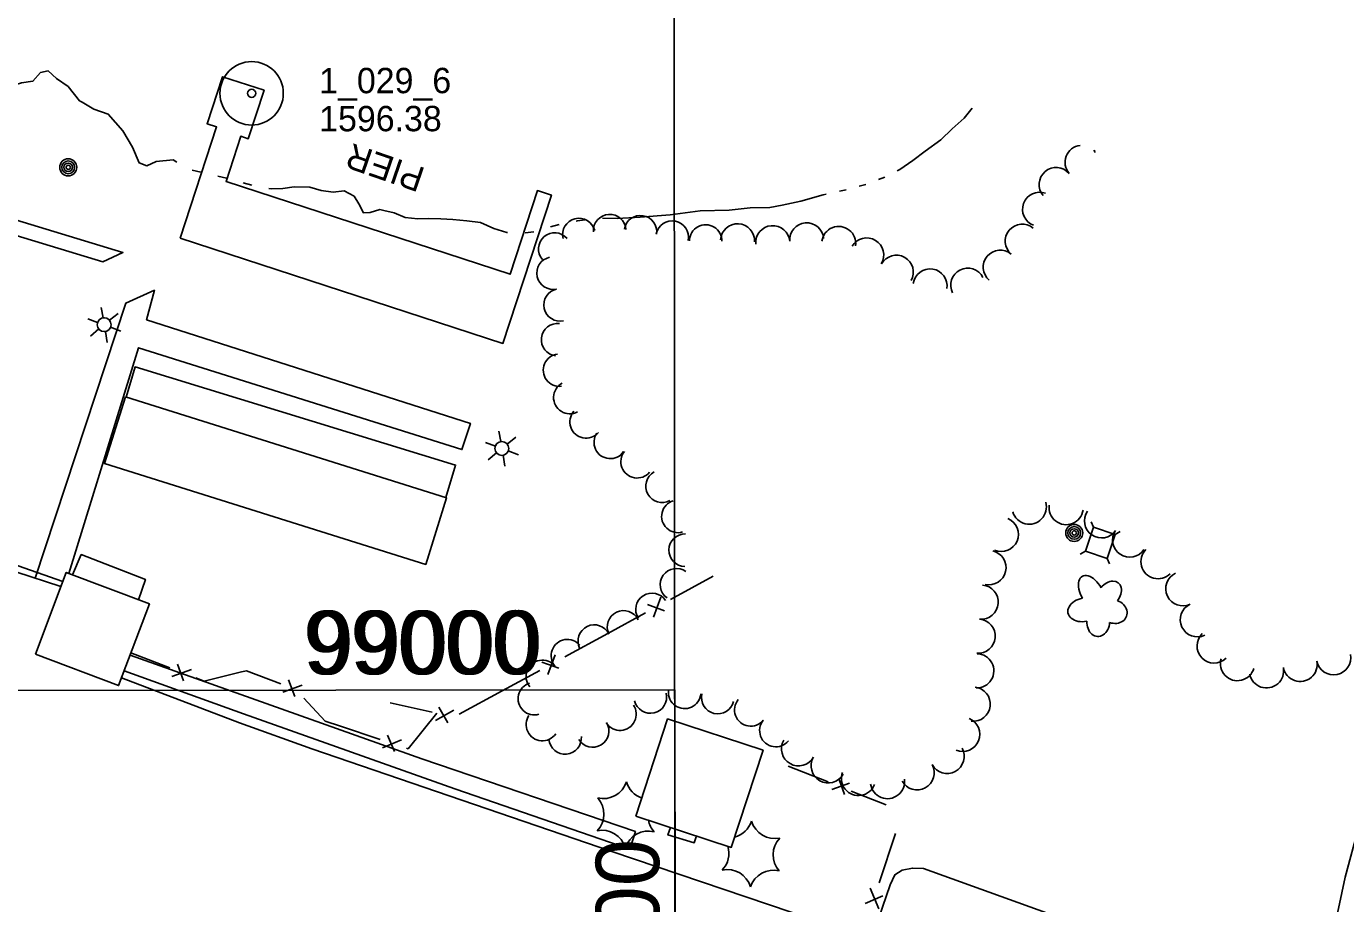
# Model space of a CAD drawing. Extents: x 189384 to 193282, y 256970 to 260388.
# Drawn here: x 191493.2 to 191805.5, y 258961.6 to 259169.2 of the extents above; entities that cross this region are included whole.
import ezdxf

# ---------------------------------------------------------------- set-up
doc = ezdxf.new("R2010")
doc.units = 0
for name, color, linetype in [('E_DWY', 7, 'Continuous'), ('E_LAND_Vegetation', 7, 'Continuous'), ('E_MAP_GridLines', 7, 'Continuous'), ('E_MAP_PassPoints', 7, 'Continuous'), ('E_MISCPROP', 7, 'Continuous'), ('E_MISCPROP_HvyDash', 7, 'Continuous'), ('E_MISCPROP_HvyLine', 7, 'Continuous'), ('E_MISCPROP_Railing', 7, 'Continuous'), ('E_PATH_Sidewalk', 7, 'Continuous'), ('E_UTL_AboveGroundPipe', 7, 'Continuous'), ('E_WTR', 7, 'Continuous'), ('E_WTR_Dock_Pier', 7, 'Continuous'), ('E_WTR_Text', 7, 'Continuous')]:
    doc.layers.add(name, color=color, linetype=linetype)

# ---------------------------------------------------------------- blocks, each defined once
blk = doc.blocks.new('PP')
at = {"layer": 'E_MAP_PassPoints'}
for radius in [7.5, 0.96]:
    blk.add_circle((0, 0), radius, dxfattribs=at)
blk = doc.blocks.new('PIER')
at = {"layer": 'E_WTR_Text'}
blk.add_text('PIER', height=6, rotation=0.0001, dxfattribs=at).set_placement((0.24, -2.75))
blk = doc.blocks.new('POLE')
at = {"layer": 'E_MISCPROP'}
for radius in [2.02, 1.51, 1.01, 0.504]:
    blk.add_circle((0.03, -0.09), radius, dxfattribs=at)
blk = doc.blocks.new('LTP')
at = {"layer": 'E_MISCPROP'}
for p, q in [((-0.78, 1.46), (-1.98, 3.76)), ((0.86, 1.37), (2.22, 3.6)), ((-1.61, 0.09), (-4.22, 0.17)), ((1.66, 0), (4.18, -0.06)), ((-0.86, -1.4), (-2.22, -3.59)), ((0.78, -1.44), (2.02, -3.62))]:
    blk.add_line(p, q, dxfattribs=at)
blk.add_circle((0.02, 0.01), 1.64, dxfattribs=at)
blk = doc.blocks.new('POLE_1')
at = {"layer": 'E_MISCPROP'}
for radius in [2.02, 1.51, 1.01, 0.504]:
    blk.add_circle((0.03, -0.09), radius, dxfattribs=at)
blk = doc.blocks.new('PED')
at = {"layer": 'E_UTL_AboveGroundPipe'}
for p, q in [((-2.34, 2.71), (-3.29, 3.77)), ((3.06, 2.71), (4.02, 3.77)), ((-3.29, -4.35), (-2.34, -3.29)), ((4.02, -4.35), (3.06, -3.29))]:
    blk.add_line(p, q, dxfattribs=at)
blk.add_lwpolyline([(-2.34, -3.29), (3.06, -3.29), (3.06, 2.71), (-2.34, 2.71)], close=True, dxfattribs=at)
blk = doc.blocks.new('TREE')
at = {"layer": 'E_LAND_Vegetation'}
for centre, major_axis, ratio in [((-1.07, 3.38), (0.91, -3.32), 0.782863), ((2.88, 1.66), (-3.52, -1.95), 0.691916), ((-3.74, -0.07), (3.29, -0.08), 0.832022), ((-1.48, -3.66), (1.2, 3.24), 0.716896), ((2.54, -2.64), (-3.34, 3.06), 0.560249)]:
    blk.add_ellipse(centre, major_axis=major_axis, ratio=ratio, start_param=1.570796, end_param=4.712389, dxfattribs=at)

msp = doc.modelspace()

# ---------------------------------------------------------------- linework, layer by layer
at = {"layer": 'E_DWY'}
for points in [[(191501.35, 259036.59), (191479.96, 259043.57)], [(191682.66, 258922.4), (191681.57, 258919.82), (191680.85, 258919.25), (191679.6, 258918.89), (191678.51, 258918.91), (191677.77, 258919.33), (191677.07, 258920.57), (191676.84, 258921.92), (191677.19, 258923.18), (191686.53, 258953.16), (191686.41, 258954.33), (191685.67, 258955.42), (191684.69, 258956.02), (191631.75, 258973.9), (191560.77, 258998.17), (191543.64, 259004.34), (191515.7, 259014.96)], [(191682.66, 258922.4), (191697.63, 258965.98), (191698.76, 258968.4), (191700.51, 258969.51), (191702.94, 258969.96), (191705.59, 258969.84), (191795.73, 258937.33), (191797.22, 258936.96), (191798.22, 258936.97), (191799.23, 258937.68), (191800.15, 258938.79), (191800.88, 258941.07), (191801.39, 258946.78), (191802.75, 258955.61), (191805.35, 258967.79), (191808.61, 258979.78)]]:
    msp.add_lwpolyline(points, dxfattribs=at)
at = {"layer": 'E_LAND_Vegetation'}
for centre, radius, start, end in [((191743.1, 259136.99), 4.03, 97.0163, 220.6033), ((191749.43, 259141.75), 4.03, 207.8807, 216.409), ((191743.1, 259136.99), 4.03, 40.6033, 44.7846), ((191736.97, 259131.74), 4.03, 40.6033, 220.6033), ((191733.02, 259125.89), 4.03, 69.7676, 249.7676), ((191623.98, 259119.9), 3.85, 13.9298, 193.9298), ((191631.27, 259120.84), 3.85, 3.7621, 183.7621), ((191638.56, 259120.57), 3.85, 351.0761, 171.0761), ((191618.25, 259116.49), 3.85, 40.642, 220.642), ((191646.06, 259119.29), 3.85, 348.3917, 168.3917), ((191654, 259118.38), 3.85, 358.8551, 178.8551), ((191661.55, 259118.43), 4.03, 356.859, 176.859), ((191669.86, 259117.99), 4.03, 4.6262, 184.6262), ((191677.9, 259118.64), 4.03, 4.6262, 184.6262), ((191685.49, 259117.8), 4.03, 352.0997, 172.0997), ((191728.92, 259118.33), 4.03, 49.7405, 229.7405), ((191692.11, 259115.07), 4.03, 329.0382, 149.0382), ((191617.86, 259110.76), 3.85, 102.5104, 282.5104), ((191699.13, 259110.99), 4.03, 330.7807, 150.7807), ((191723.71, 259112.17), 4.03, 49.7405, 229.7405), ((191707.12, 259107.74), 4.03, 351.304, 171.304), ((191716.04, 259107.93), 4.03, 27.2617, 207.2617), ((191619.53, 259103.25), 3.85, 102.5104, 282.5104), ((191618.93, 259095.02), 3.85, 83.0216, 263.0216), ((191619.4, 259087.81), 3.85, 96.6718, 276.6718), ((191621.84, 259081.33), 3.85, 117.809, 297.809), ((191625.69, 259075.56), 3.85, 138.7581, 318.7581), ((191631.41, 259070.73), 3.85, 145.1067, 325.1067), ((191637.76, 259066.13), 3.85, 140.267, 320.267), ((191643.67, 259060.35), 3.85, 119.015, 299.015), ((191647.42, 259053.2), 3.85, 106.5727, 286.5727), ((191730.59, 259055.4), 4.05, 196.4577, 16.4577), ((191739.34, 259055.29), 4.05, 171.4708, 351.4708), ((191723.96, 259048.95), 4.05, 247.1666, 67.1666), ((191747.69, 259052.15), 4.05, 145.4967, 325.4967), ((191649.14, 259045.2), 3.85, 88.7862, 268.7862), ((191754.36, 259047.6), 4.05, 146.2308, 326.2308), ((191721.05, 259041.07), 4.05, 257.1069, 77.1069), ((191761.07, 259042.5), 4.05, 135.0828, 315.0828), ((191647.08, 259037.03), 3.85, 54.5609, 234.5609), ((191766.94, 259036.08), 4.05, 115.1992, 295.1992), ((191719.2, 259032.92), 4.05, 265.0495, 85.0495), ((191641.28, 259031.2), 3.85, 33.0671, 213.0671), ((191634.54, 259027.05), 3.85, 25.9648, 205.9648), ((191770.39, 259028.75), 4.05, 115.1992, 295.1992), ((191627.62, 259023.69), 3.85, 25.9648, 205.9648), ((191718.5, 259024.85), 4.05, 265.0495, 85.0495), ((191621.26, 259020.24), 3.85, 39.6031, 219.6031), ((191774.36, 259022.54), 4.05, 134.0217, 314.0217), ((191718.15, 259016.64), 4.05, 268.5318, 88.5318), ((191802.64, 259019.74), 4.05, 191.4446, 11.4446), ((191615.33, 259015.34), 3.85, 39.6031, 219.6031), ((191779.87, 259018.36), 4.05, 163.3782, 343.3782), ((191786.76, 259016.65), 4.05, 190.8536, 10.8536), ((191794.72, 259018.18), 4.05, 190.8536, 10.8536), ((191613.43, 259010.06), 3.85, 106.6763, 286.6763), ((191640.9, 259010.46), 3.85, 193.4275, 13.4275), ((191649.01, 259011.56), 3.85, 174.7182, 354.7182), ((191656.85, 259010.32), 3.85, 166.4636, 346.4636), ((191717.32, 259008.75), 4.05, 263.6699, 83.6699), ((191633.71, 259006.41), 3.85, 213.7749, 33.7749), ((191664.68, 259007.41), 3.85, 140.4956, 320.4956), ((191615.33, 259003.93), 3.85, 145.468, 325.468), ((191670.61, 259002.52), 3.85, 140.4956, 320.4956), ((191714.84, 259001.64), 4.05, 247.8067, 67.8067), ((191627.23, 259002.42), 3.85, 211.1427, 31.1427), ((191620.73, 259000.78), 3.85, 185.095, 5.095), ((191675.97, 258998.2), 4.05, 150.2066, 330.2066), ((191682.99, 258994.17), 4.05, 150.2066, 330.2066), ((191711.14, 258996.4), 4.05, 208.7484, 28.7484), ((191690.18, 258991.19), 4.05, 159.2841, 339.2841), ((191704.04, 258992.51), 4.05, 208.7484, 28.7484), ((191629.8, 258992.14), 5.72, 256.1722, 341.9371), ((191640.74, 258991.95), 5.72, 196.1722, 250.7154), ((191697.03, 258990.44), 4.05, 188.4202, 8.4202), ((191624.17, 258982.75), 5.72, 316.1722, 41.9371), ((191646.05, 258982.39), 5.72, 190.9701, 221.9371), ((191659.41, 258982.86), 5.72, 284.4103, 341.9371), ((191670.35, 258982.68), 5.72, 196.1722, 281.9371), ((191629.49, 258973.19), 5.72, 16.1722, 101.9371), ((191640.43, 258973.01), 5.72, 76.1722, 161.9371), ((191675.66, 258973.12), 5.72, 136.1722, 221.9371), ((191653.78, 258973.48), 5.72, 316.1722, 16.7627), ((191659.1, 258963.91), 5.72, 16.1722, 101.9371), ((191670.03, 258963.73), 5.72, 76.1722, 161.9371)]:
    msp.add_arc(centre, radius, start, end, dxfattribs=at)
at = {"layer": 'E_MAP_GridLines'}
for p, q in [((191647.04, 258512.16), (191646.33, 259512.15)), ((190146.69, 259011.09), (191646.69, 259012.15)), ((190146.69, 259011.09), (191646.69, 259012.15)), ((190146.69, 259011.09), (191646.69, 259012.15)), ((191647.75, 257512.16), (191646.69, 259012.15))]:
    msp.add_line(p, q, dxfattribs=at)
at = {"layer": 'E_MISCPROP_HvyDash'}
for points in [[(191516.83, 259081.43), (191518.94, 259088.56), (191594.78, 259065.35), (191592.48, 259057.65)], [(191504.1, 259039.38), (191506.19, 259044.15), (191521.37, 259038.3), (191519.72, 259033.47)]]:
    msp.add_lwpolyline(points, dxfattribs=at)
at = {"layer": 'E_MISCPROP_HvyLine'}
for points in [[(191516.62, 259081.5), (191592.67, 259057.59), (191592.67, 259057.59), (191592.67, 259057.59), (191587.71, 259041.83), (191587.71, 259041.83), (191511.66, 259065.73), (191516.62, 259081.5)], [(191495.31, 259020.62), (191495.31, 259020.62), (191515.02, 259013.17), (191515.02, 259013.17), (191522.33, 259032.49), (191522.33, 259032.49), (191502.62, 259039.94), (191495.31, 259020.62)], [(191637.45, 258982.28), (191644.98, 259005.27), (191644.98, 259005.27), (191644.98, 259005.27), (191667.57, 258997.87), (191667.57, 258997.87), (191660.03, 258974.88)]]:
    msp.add_lwpolyline(points, close=True, dxfattribs=at)
at = {"layer": 'E_MISCPROP_Railing'}
for p, q in [((191641.62, 259029.35), (191643.38, 259034.07)), ((191640.19, 259032.34), (191644.25, 259030.86)), ((191616.63, 259015.75), (191618.39, 259020.47)), ((191528.95, 259018.24), (191530.4, 259014.29)), ((191615.2, 259018.74), (191619.26, 259017.26)), ((191527.63, 259015.3), (191532.24, 259016.96)), ((191555.21, 259014.53), (191556.7, 259010.6)), ((191553.92, 259011.57), (191558.51, 259013.28)), ((191590.85, 259008.07), (191592.98, 259004.32)), ((191590, 259004.87), (191594.39, 259007.33)), ((191577.49, 258998.41), (191582.02, 259000.29)), ((191578.68, 259001.41), (191580.31, 258997.53)), ((191688.05, 258990.03), (191683.89, 258988.56)), ((191686.84, 258987.4), (191685.56, 258990.95)), ((191694.99, 258960.31), (191692.93, 258965.24)), ((191691.72, 258961.59), (191695.93, 258963.38))]:
    msp.add_line(p, q, dxfattribs=at)
for points in [[(191489.66, 259042.05), (191501.81, 259037.79)], [(191645.64, 259033.56), (191655.79, 259039.09)], [(191630.8, 259025.49), (191639.73, 259030.35)], [(191620.65, 259019.96), (191630.8, 259025.49)], [(191517.94, 259020.9), (191527.18, 259017.33)], [(191533.28, 259014.96), (191535.24, 259014.2), (191544.14, 259016.38)], [(191544.14, 259016.38), (191545.31, 259016.67), (191553.45, 259013.6)], [(191605.81, 259011.88), (191614.74, 259016.74)], [(191595.66, 259006.36), (191605.81, 259011.88)], [(191558.84, 259010.2), (191563.94, 259004.77), (191567.56, 259003.56)], [(191579.29, 259009.1), (191589.21, 259006.87)], [(191583.15, 258998.33), (191583.56, 258998.2), (191590.39, 259006.61)], [(191567.56, 259003.56), (191576.95, 259000.41)], [(191682.97, 258990.36), (191673.55, 258994.07)], [(191696.72, 258984.95), (191688.44, 258988.21)], [(191695.05, 258966.48), (191698.91, 258978.13)]]:
    msp.add_lwpolyline(points, dxfattribs=at)
at = {"layer": 'E_PATH_Sidewalk'}
for points in [[(191490.8, 259119.66), (191511.31, 259113.43), (191516.04, 259115.64), (191479.61, 259126.72), (191478.93, 259125.01)], [(191495.28, 259038.57), (191516.71, 259103.65), (191523.5, 259106.72), (191521.63, 259099.74), (191598.29, 259075.2), (191596.29, 259069.02), (191519.73, 259093.13), (191503.24, 259039.71)], [(191517.73, 259020.35), (191586.82, 258995.83), (191637.36, 258978.6), (191636.03, 258974.44), (191594.65, 258988.76), (191544.59, 259006.46), (191516.33, 259016.63)], [(191645.63, 258979.6), (191645.06, 258977.8), (191651.3, 258975.95), (191651.82, 258977.57)]]:
    msp.add_lwpolyline(points, dxfattribs=at)
at = {"layer": 'E_WTR'}
for points in [[(191506.39, 259151.22), (191505.77, 259151.59), (191503.09, 259154.92), (191500.31, 259156.87), (191498.34, 259158.63), (191496.52, 259158.23), (191494.72, 259156.17), (191492.04, 259155.85), (191489.72, 259155.13), (191487.6, 259154.19), (191486.5, 259153.69), (191486.42, 259154.91), (191487.97, 259157.95), (191488.36, 259159.05)], [(191528.81, 259137.04), (191527.95, 259137.61), (191523.91, 259137.2), (191521.7, 259136.16), (191519.9, 259136.85), (191518.29, 259140.58), (191516.04, 259144.45), (191512.56, 259148.39), (191509.17, 259149.54), (191506.39, 259151.22)], [(191699.31, 259134.98), (191699.98, 259135.33), (191703.04, 259137.44), (191705.98, 259139.65), (191709.65, 259142.32), (191712.32, 259144.89), (191715.2, 259147.43), (191717.1, 259149.83)], [(191534.48, 259134.66), (191532.45, 259135.13)], [(191540.53, 259133.22), (191538.52, 259133.7)], [(191694.94, 259132.91), (191696.44, 259133.49)], [(191546.54, 259131.57), (191544.54, 259132.15)], [(191577.79, 259125.6), (191576.85, 259125.81), (191574.57, 259125.09), (191572.96, 259125.08), (191571.88, 259127.14), (191570.76, 259129.01), (191568.41, 259130.23), (191565.78, 259129.96), (191563.01, 259130.3), (191560.3, 259131.12), (191556.6, 259131.16), (191553.88, 259130.84), (191551.18, 259130.76), (191550.61, 259130.83)], [(191685.67, 259130.15), (191687.25, 259130.5)], [(191690.36, 259131.35), (191691.92, 259131.78)], [(191659.52, 259125.68), (191664.51, 259126.21), (191669.17, 259126.31), (191672.09, 259126.83), (191676.48, 259127.84), (191681.82, 259129.29), (191682.52, 259129.44)], [(191607.11, 259120.4), (191606.95, 259120.4), (191603.85, 259121.34), (191600.68, 259122.74), (191597.43, 259123.19), (191594.1, 259123.44), (191591.29, 259123.64), (191588.49, 259123.74), (191585.85, 259123.66), (191582.89, 259123.94), (191580.26, 259125.04), (191577.79, 259125.6)], [(191659.52, 259125.68), (191652.69, 259125.54), (191645.56, 259124.55), (191638.49, 259124.04), (191633.06, 259123.68), (191629.53, 259123.78)], [(191613.32, 259120.55), (191611.25, 259120.32)], [(191619.29, 259122.26), (191617.29, 259121.71)], [(191625.41, 259123.4), (191623.63, 259123.16), (191623.35, 259123.1)]]:
    msp.add_lwpolyline(points, dxfattribs=at)
at = {"layer": 'E_WTR_Dock_Pier'}
msp.add_lwpolyline([(191529.61, 259119.07), (191606.01, 259094.14), (191617.46, 259129.25), (191614.16, 259130.33), (191607.69, 259110.49), (191540.45, 259132.43), (191543.95, 259143.15), (191545.7, 259142.58), (191549.45, 259154.07), (191539.62, 259157.27), (191535.98, 259146.11), (191538.2, 259145.39)], close=True, dxfattribs=at)

# ---------------------------------------------------------------- block references
at = {"layer": 'E_LAND_Vegetation', "rotation": 161.72867749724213}
msp.add_blockref('TREE', (191746.96, 259031.78), dxfattribs=at)
at = {"layer": 'E_MAP_PassPoints', "rotation": 0.04070112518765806}
msp.add_blockref('PP', (191546.51, 259153.33), dxfattribs=at)
msp.add_blockref('PP', (191546.51, 259153.33), dxfattribs=at)
at = {"layer": 'E_MISCPROP'}
for name, p, xscale, yscale, rotation in [('POLE', (191503.09, 259135.72), 1.0000017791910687, 1.000001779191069, 160.96089259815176), ('LTP', (191511.63, 259098.57), 1.000001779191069, 1.000001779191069, 160.96089244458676), ('LTP', (191605.77, 259069.29), 1.0000017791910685, 1.0000017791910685, 160.96089076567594)]:
    msp.add_blockref(name, p, dxfattribs=dict(at, xscale=xscale, yscale=yscale, rotation=rotation))
at = {"layer": 'E_MISCPROP', "rotation": 161.72867759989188}
msp.add_blockref('POLE_1', (191741.23, 259049.19), dxfattribs=at)
at = {"layer": 'E_UTL_AboveGroundPipe', "rotation": 161.72867748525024}
msp.add_blockref('PED', (191747.66, 259046.55), dxfattribs=at)
at = {"layer": 'E_WTR_Text', "xscale": 1.0000017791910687, "yscale": 1.000001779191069, "rotation": 160.96089109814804}
msp.add_blockref('PIER', (191587.24, 259132.84), dxfattribs=at)

# ---------------------------------------------------------------- texts
at = {"layer": 'E_MAP_GridLines'}
for s, rotation, p in [('  99000  ', 0.0407, (191547.58, 259015.83)), ('  99000  ', 0.0407, (191548.35, 259015.83)), ('  388500  ', 90.0407, (191643.02, 258898.76))]:
    msp.add_text(s, height=15, rotation=rotation, dxfattribs=at).set_placement(p)
at = {"layer": 'E_MAP_PassPoints'}
for s, p in [('1_029_6', (191562.51, 259153.34)), ('1_029_6', (191562.51, 259153.34)), ('1596.38', (191562.51, 259144.34)), ('1596.38', (191562.51, 259144.34))]:
    msp.add_text(s, height=6, rotation=0.0407, dxfattribs=at).set_placement(p)

doc.saveas('drawing.dxf')
